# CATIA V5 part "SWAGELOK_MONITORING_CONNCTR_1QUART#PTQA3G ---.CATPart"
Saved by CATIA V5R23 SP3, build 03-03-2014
Part number: SWAGELOK_MONITORING_CONNCTR_1QUART#PTQA2Y
Revision: ---
Nomenclature: _
Description: SWAGELOK_MONITORING_CONNCTR_1QUA
Property "ID": "PTQA2Y"
Property "AT": "PD"
Property "REP": "CM"
Property "External Part ID": "_"
Property "Description Modification": "StandardPartcreation"
Property "PREF": "Y"
Property "LONG": "_"
Property "PBS 1": "24"
Property "PBS 2": "--"
Property "PBS 3": "--"
Property "DEPT": "_"
Property "DIVN": "_"
Property "GROUP": "_"
Property "UNIT": "_"
Property "PARTY": "_"
Property "RO": "---"
Property "RE": "SEKACHI"
Property "PRO": "---"
Property "Change Type": "Major"
Property "Maturity Level": "CD"
Property "Export Number": "_"
Property "Description Documents": "_"
Property "BOM": "_"
Property "User In Enovia": "BERQUEJ"
Property "Object Type": "_"
Property "CADENAS_ID": "_"
Property "Life Cycle Status": "Approved"
Material "Stainless steel": density 8030 kg/m3, Young's modulus 2e+11 Pa, Poisson ratio 0.266, thermal expansion 1.17e-05 1/K
Bounding box of the stored display mesh (mm): x -7.935 to 7.935, y -9.163 to 9.163, z -11.5 to 22
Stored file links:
  C:\Users\pandeym\Desktop\__TCPH\SWAGELOK_MONITORING_CONNCTR_1QUART#PTQA3G ---.CATPart
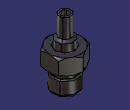
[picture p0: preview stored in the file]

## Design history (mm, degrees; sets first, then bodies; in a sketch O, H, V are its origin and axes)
Body1 (main body)
  Sketch1 on xy-plane, origin (0, 0, 0), H (1, 0, 0), V (0, 1, 0)
    point P1 (7.935, -4.5813)
    point P2 (7.935, 4.5813)
    point P3 (0, 9.1625)
    point P4 (-7.935, 4.5813)
    point P5 (-7.935, -4.5813)
    point P6 (0, -9.1625)
    point P7 (7.935, 0)
    line L1 (7.935, -4.5813) -> (7.935, 4.5813)
    line L2 (7.935, 4.5813) -> (0, 9.1625)
    line L3 (0, 9.1625) -> (-7.935, 4.5813)
    line L4 (-7.935, 4.5813) -> (-7.935, -4.5813)
    line L5 (-7.935, -4.5813) -> (0, -9.1625)
    line L6 (0, -9.1625) -> (7.935, -4.5813)
    construction line L7 (0, 0) -> (7.935, 0)
    construction circle A1 centre (0, 0) radius 9.1625
    construction arc A2 centre (-7.935, -4.5813) radius 9.1625 from (-7.935, 4.5813) to (0, -9.1625) cw
    construction arc A3 centre (7.935, 4.5813) radius 9.1625 from (0, 9.1625) to (7.935, -4.5813) ccw
    circle A4 centre (0, 0) radius 4.55
    radius A4 = 4.55
    distance L1 L4 = 15.87
    horizontal: L7 H
    coincidence: A1 P1, A1 P2, A1 P3, A1 P4, A1 P5, A1 P6, A2 O, A3 O
    midpoint: P7 L1
  Pad1: profile Sketch1, direction (0, 0, 1), length 8
  Sketch2 on zx-plane, origin (0, 0, 0), H (-1, 0, 0), V (0, 0, 1)
    line L1 (4.55, 0) -> (4.55, -10)
    line L2 (4.55, -10) -> (6.55, -10)
    line L3 (6.55, -10) -> (6.55, -3)
    line L4 (6.55, -3) -> (5.55, -3)
    line L5 (5.55, -3) -> (5.55, 0)
    line L6 (5.55, 0) -> (4.55, 0)
    reference intersected line E1 through (0, 0) direction (-1, 0) from start face of Pad1
    distance L1 V = 4.55
    distance L5 L1 = 1
    length L2 = 2
    length L1 = 10
    length L3 = 7
    vertical: L1 V, L3 V, L5 V
    horizontal: L2 H, L4 H, L6 H
    coincidence: L6 E1
  Shaft1: profile Sketch2, axis axis of face of Pad1 from Sketch1.A4, angle 360
  Thread1: diameter 13.1, depth 7, pitch 1, on face of Shaft1 from Sketch2.L3, from face of Shaft1 from Sketch2.L2
  Chamfer1: length 0.5, angle 45, on face of Shaft1 from Sketch2.L1; face of Shaft1 from Sketch2.L3
  Sketch3 on yz-plane, origin (0, 0, 0), H (0, 1, 0), V (0, 0, 1)
    point P1 (8, 8)
    line L1 (8, 8) -> (8, 9)
    line L2 (8, 9) -> (11, 9)
    line L3 (11, 9) -> (11, -1)
    line L4 (11, -1) -> (8, -1)
    point P5 (8, -1)
    line L5 (8, -1) -> (8, 0)
    point P6 (8, 0)
    line L6 (9.5, 6.75) -> (9.5, 1.25)
    arc A1 centre (4.8864, 2.7387) radius 6.1136 from (8, 8) to (9.5, 6.75) cw
    arc A2 centre (4.8864, 5.2613) radius 6.1136 from (8, 0) to (9.5, 1.25) ccw
    point P11 (8, 0)
    reference projected line E1 through (0, 0) direction (0, 1) from axis of face of Shaft1 from Sketch2.L5
    reference projected line E2 through (0, 0) direction (0, 1) from axis of face of Shaft1 from Sketch2.L5
    reference projected line E3 (4.5813, 0) -> (9.1625, 0) from edge [start face of Pad1 | face of Pad1 from Sketch1.L2]
    reference intersected line E4 through (0, 8) direction (-1, 0) from end face of Pad1
    axis line L7 (2.6271, 4) -> (14.2922, 4)
    reference intersected line E5 through (0, 8) direction (-1, 0) from end face of Pad1
    reference intersected line E6 through (0, 0) direction (-1, 0) from start face of Pad1
    length L1 = 1
    length L5 = 1
    distance L3 E1 = 11
    distance L6 E2 = 9.5
    length L2 = 3
    length L6 = 5.5
    vertical: L1 V, L3 V, L5 V, L6 V
    horizontal: L2 H, L4 H, L7 H
    coincidence: P5 L1, A2 P11, P11 H, P6 E3, P1 E4
    tangency: A2 L3
    symmetry: E5 E6 L7, A1 A2 L7
  Groove1: profile Sketch3, axis axis of face of Shaft1 from Sketch2.L5, angle 360
  Sketch4 on zx-plane, origin (0, 0, 0), H (-1, 0, 0), V (0, 0, 1)
    line L1 (2, 22) -> (2, -11.5)
    line L2 (2, -11.5) -> (4.5, -11.5)
    line L3 (4.5, -11.5) -> (4.5, -11)
    line L4 (4.5, -11) -> (5, -11)
    line L5 (5, -11) -> (5, -10.5)
    line L6 (5, -10.5) -> (6, -10.5)
    line L7 (6, -10.5) -> (6, -10)
    line L8 (6, -10) -> (4.5, -10)
    line L9 (4.5, -10) -> (4.5, 11.5)
    point P10 (4.5, 11.5)
    line L10 (4.5, 11.5) -> (3, 12.4)
    line L11 (3, 12.4) -> (3, 22)
    line L12 (3, 22) -> (2, 22)
    axis line L13 (0, 31.4235) -> (0, -16.4076)
    point P13 (0, 31.4235)
    reference intersected line E1 through (0, -10) direction (-1, 0) from face of Shaft1 from Sketch2.L2
    reference projected line E2 through (0, 0) direction (0, 1) from axis of face of Shaft1 from Sketch2.L3
    distance L9 L13 = 4.5
    length L1 = 33.5
    length L11 = 9.6
    distance L12 P10 = 10.5
    distance L11 L1 = 1
    length L7 = 0.5
    distance E2 L7 = 6
    distance L5 L7 = 1
    distance L8 L2 = 1.5
    distance L4 L8 = 1
    length L2 = 2.5
    distance L11 L13 = 3
    vertical: L1 V, L3 V, L5 V, L7 V, L9 V, L11 V, L13 V
    horizontal: L2 H, L4 H, L6 H, L8 H, L12 H
    coincidence: P13 V, L8 E1
Body2
  Shaft2: profile Sketch4, axis axis of face of Shaft1 from Sketch2.L1, angle 360
  Chamfer2: length 0.3, angle 45, on edge [face of Shaft2 from Sketch4.L2 | face of Shaft2 from Sketch4.L3]
  Chamfer3: length 0.5, angle 45, on edge [face of Shaft2 from Sketch4.L1 | face of Shaft2 from Sketch4.L2]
